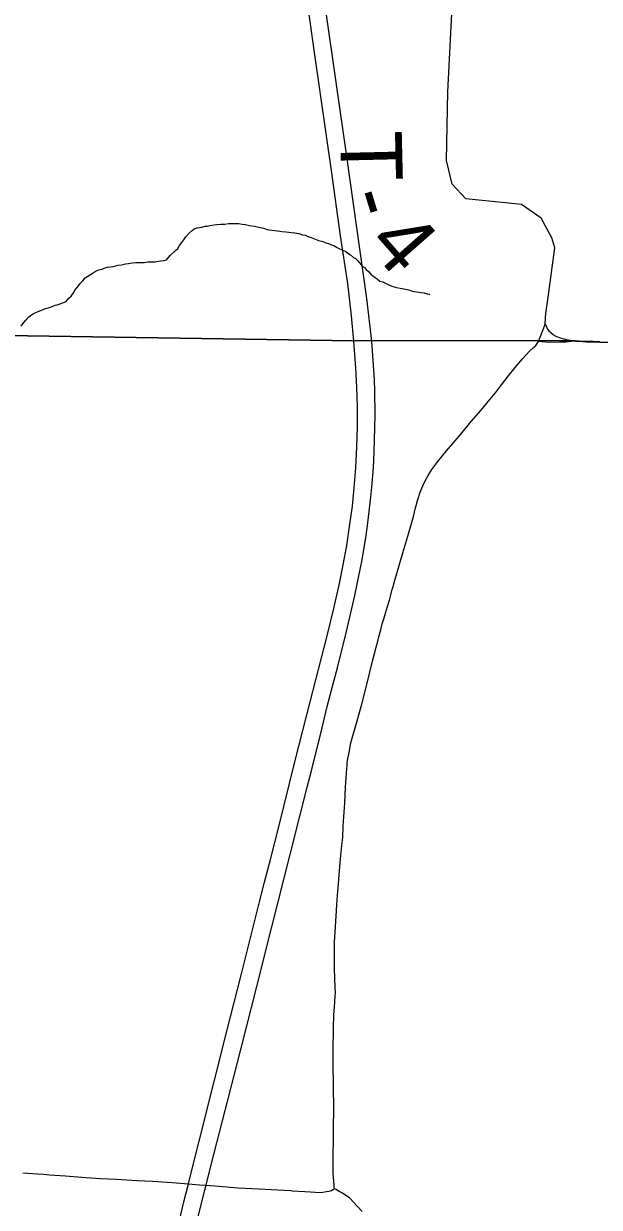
# Model space of a CAD drawing. Extents: x -14196 to 143, y -6096 to 28.
# Drawn here: x 60.591 to 61.122, y 18.007 to 19.098 of the extents above; entities that cross this region are included whole.
import ezdxf

# ---------------------------------------------------------------- set-up
doc = ezdxf.new("R2010")
doc.units = 0
for name, color, linetype in [('GM_X_Corporation', 7, 'Continuous'), ('GM_X_Interstate_Route', 7, 'Continuous'), ('GM_X_Minor_River', 7, 'Continuous'), ('GM_X_Township_Road', 7, 'Continuous'), ('GM_X_Township_Road_Text', 7, 'Continuous')]:
    doc.layers.add(name, color=color, linetype=linetype)

msp = doc.modelspace()

# ---------------------------------------------------------------- linework, layer by layer
at = {"layer": 'GM_X_Corporation'}
for points in [[(59.8722, 18.8218), (60.8954, 18.8061), (60.912, 18.8063), (61.0983, 18.8061), (61.0996, 18.806), (61.1035, 18.8058), (61.1096, 18.8055), (61.116, 18.8053), (61.1223, 18.8051)], [(61.1223, 18.8051), (61.116, 18.8053), (61.1096, 18.8055), (61.1035, 18.8058), (61.0996, 18.806), (61.0983, 18.8061), (60.912, 18.8063), (60.8954, 18.8061), (59.8722, 18.8218)], [(61.1223, 18.8051), (61.116, 18.8053), (61.1096, 18.8055), (61.1035, 18.8058), (61.0996, 18.806), (61.0983, 18.8061), (60.912, 18.8063), (60.8954, 18.8061), (59.8722, 18.8218)], [(59.8722, 18.8218), (60.8954, 18.8061), (60.912, 18.8063), (61.0983, 18.8061), (61.0996, 18.806), (61.1035, 18.8058), (61.1096, 18.8055), (61.116, 18.8053), (61.1223, 18.8051)]]:
    msp.add_lwpolyline(points, dxfattribs=at)
at = {"layer": 'GM_X_Interstate_Route'}
for points in [[(60.9122, 18.8058), (60.9074, 18.845), (60.8892, 18.9758), (60.8693, 19.1129), (60.8405, 19.3186), (60.8277, 19.4083), (60.8186, 19.4759), (60.8137, 19.5147), (60.8102, 19.5418), (60.8094, 19.5798), (60.8096, 19.619), (60.8115, 19.6474), (60.8138, 19.6739), (60.8196, 19.7099), (60.8268, 19.747)], [(60.8956, 18.8056), (60.8934, 18.8292), (60.8899, 18.8588), (60.8833, 18.9029), (60.8749, 18.9631), (60.8596, 19.0697), (60.8503, 19.1355), (60.8427, 19.1883), (60.8363, 19.235), (60.8284, 19.299), (60.8241, 19.3296), (60.8155, 19.3923), (60.8086, 19.4392), (60.8021, 19.4892), (60.7981, 19.524), (60.797, 19.5612), (60.797, 19.6), (60.796, 19.6301), (60.7968, 19.6533), (60.7993, 19.6773), (60.8042, 19.7129)], [(60.7311, 17.9793), (60.7389, 18.0125), (60.7431, 18.0291), (60.744, 18.033), (60.7529, 18.0686), (60.7671, 18.1246), (60.7785, 18.1697), (60.7919, 18.2227), (60.8087, 18.289), (60.8133, 18.307), (60.8186, 18.3281), (60.826, 18.357), (60.8412, 18.4179), (60.8523, 18.4612), (60.8712, 18.5353), (60.8772, 18.5594), (60.8823, 18.5825), (60.8858, 18.5996), (60.889, 18.6173), (60.892, 18.637), (60.8942, 18.6537), (60.8959, 18.6704), (60.8973, 18.689), (60.8983, 18.7082), (60.8988, 18.7269), (60.8988, 18.7456), (60.8984, 18.763), (60.8975, 18.781), (60.8956, 18.8056)], [(60.7518, 17.9978), (60.7581, 18.0232), (60.7593, 18.0279), (60.7641, 18.0466), (60.7769, 18.0966), (60.7852, 18.129), (60.7917, 18.1543), (60.8061, 18.2109), (60.8198, 18.2659), (60.8368, 18.3326), (60.8459, 18.3681), (60.8524, 18.3946), (60.8561, 18.4084), (60.8604, 18.426), (60.8634, 18.4367), (60.8664, 18.4494), (60.871, 18.4689), (60.8766, 18.4898), (60.8805, 18.5048), (60.8888, 18.538), (60.8965, 18.5712), (60.9017, 18.5968), (60.9031, 18.6041), (60.9068, 18.6267), (60.9085, 18.6384), (60.9113, 18.6618), (60.9122, 18.6711), (60.9136, 18.689), (60.9144, 18.7039), (60.915, 18.7256), (60.9151, 18.738), (60.9148, 18.7597), (60.9146, 18.7703), (60.9122, 18.8058)]]:
    msp.add_lwpolyline(points, dxfattribs=at)
at = {"layer": 'GM_X_Minor_River'}
for points in [[(60.589, 18.8194), (60.5912, 18.8229), (60.5931, 18.8252), (60.5957, 18.8279), (60.5976, 18.8294), (60.5998, 18.831), (60.6029, 18.8325), (60.607, 18.8341), (60.6097, 18.8352), (60.6127, 18.836), (60.615, 18.8368), (60.6176, 18.8376), (60.6202, 18.8388), (60.6221, 18.8392), (60.624, 18.8399), (60.6305, 18.8423), (60.6327, 18.8453), (60.635, 18.8473), (60.6372, 18.8503), (60.6387, 18.853), (60.6402, 18.8549), (60.6417, 18.8568), (60.6432, 18.8587), (60.6458, 18.8614), (60.648, 18.8641), (60.6503, 18.8656), (60.6529, 18.8672), (60.6552, 18.8687), (60.6571, 18.8699), (60.6597, 18.8711), (60.6616, 18.8718), (60.6635, 18.8722), (60.6654, 18.873), (60.6681, 18.8738), (60.6711, 18.8742), (60.6737, 18.8746), (60.6783, 18.8758), (60.6813, 18.8762), (60.6851, 18.877), (60.6878, 18.8774), (60.6912, 18.8778), (60.6946, 18.8782), (60.6984, 18.8783), (60.7022, 18.8783), (60.7056, 18.8787), (60.7086, 18.8788), (60.712, 18.8788), (60.7174, 18.8796), (60.7208, 18.88), (60.7227, 18.8808), (60.7264, 18.885), (60.7313, 18.8893), (60.7332, 18.8912), (60.7347, 18.8938), (60.7369, 18.8965), (60.7388, 18.8992), (60.7406, 18.9019), (60.7436, 18.9053), (60.7466, 18.9076), (60.7485, 18.9092), (60.7512, 18.91), (60.7534, 18.9104), (60.7553, 18.9108), (60.7584, 18.9116), (60.7603, 18.9116), (60.7629, 18.9124), (60.7667, 18.9128), (60.7694, 18.9132), (60.7728, 18.9136), (60.7766, 18.9136), (60.78, 18.9141), (60.7823, 18.9141), (60.7853, 18.9141), (60.7891, 18.9141), (60.7925, 18.9134), (60.7956, 18.9131), (60.7994, 18.9123), (60.8039, 18.9116), (60.8081, 18.9109), (60.8123, 18.9098), (60.8157, 18.9087), (60.8199, 18.908), (60.8226, 18.9076), (60.8256, 18.9073), (60.8291, 18.9069), (60.8329, 18.9066), (60.8355, 18.9063), (60.8382, 18.9059), (60.8412, 18.9056), (60.8447, 18.9048), (60.8481, 18.9037), (60.8511, 18.9034), (60.853, 18.9023), (60.8561, 18.9011), (60.8607, 18.8993), (60.863, 18.8986), (60.8656, 18.8978), (60.8679, 18.8971), (60.8698, 18.8963)], [(60.8698, 18.8963), (60.8721, 18.8956), (60.8748, 18.8945), (60.8771, 18.8938), (60.8801, 18.8919), (60.8824, 18.8908), (60.8855, 18.8897), (60.8882, 18.8882), (60.8901, 18.8867), (60.8924, 18.8852), (60.8951, 18.8829), (60.897, 18.8818), (60.8989, 18.8799), (60.9008, 18.878), (60.9035, 18.8746), (60.9054, 18.8735), (60.907, 18.8716), (60.9089, 18.8698), (60.9112, 18.8675), (60.9143, 18.8649), (60.9169, 18.863), (60.9196, 18.8611), (60.9223, 18.8604), (60.9246, 18.8593), (60.9273, 18.8578), (60.9307, 18.8563), (60.9349, 18.8552), (60.9383, 18.8545), (60.9402, 18.8541), (60.9463, 18.853), (60.9494, 18.8519), (60.9513, 18.8516), (60.9535, 18.8512), (60.9554, 18.8509), (60.9573, 18.8505), (60.9604, 18.8501), (60.9631, 18.8494), (60.965, 18.8491), (60.9657, 18.8491)]]:
    msp.add_lwpolyline(points, dxfattribs=at)
at = {"layer": 'GM_X_Township_Road'}
for points in [[(61.0659, 18.8055), (61.0715, 18.8203), (61.0719, 18.8221), (61.0726, 18.8316), (61.074, 18.8415), (61.0807, 18.8916), (61.0779, 18.901), (61.0681, 18.9189), (61.0502, 18.9316), (60.9987, 18.937), (60.9863, 18.9503), (60.9808, 18.9722), (60.9822, 19.0354), (60.9883, 19.1563)], [(61.0985, 18.8056), (61.093, 18.8066), (61.092, 18.8068), (61.0897, 18.8074), (61.0891, 18.8076), (61.087, 18.8082), (61.0845, 18.809), (61.0836, 18.8094), (61.0819, 18.8101), (61.0794, 18.8114), (61.0767, 18.8138), (61.0759, 18.8146), (61.0753, 18.8155), (61.0747, 18.8164), (61.0738, 18.8178), (61.073, 18.8194), (61.0726, 18.8203), (61.0719, 18.8221)], [(60.8778, 18.0246), (60.8775, 18.0264), (60.8773, 18.0286), (60.877, 18.0313), (60.8766, 18.039), (60.8765, 18.0523), (60.8767, 18.0731), (60.8769, 18.083), (60.877, 18.0963), (60.877, 18.1029), (60.8769, 18.1138), (60.8767, 18.1238), (60.8764, 18.1345), (60.8765, 18.1438), (60.8766, 18.1575), (60.8769, 18.1667), (60.8769, 18.1725), (60.8772, 18.1849), (60.8777, 18.192), (60.878, 18.1968), (60.8783, 18.2021), (60.8785, 18.2053), (60.8783, 18.21), (60.878, 18.2186), (60.8778, 18.2271), (60.8776, 18.237), (60.8776, 18.2446), (60.8777, 18.252), (60.8782, 18.2613), (60.8792, 18.2759), (60.8799, 18.2867), (60.8805, 18.2952), (60.8812, 18.3019), (60.8824, 18.3178), (60.8833, 18.3285), (60.8846, 18.3408), (60.8854, 18.3482), (60.8858, 18.3587), (60.8871, 18.3803), (60.8878, 18.3947), (60.8891, 18.412), (60.8893, 18.4144), (60.8894, 18.4167), (60.8897, 18.4193), (60.8911, 18.4267), (60.8929, 18.4356), (60.8992, 18.458), (60.9031, 18.4725), (60.9066, 18.4857), (60.9101, 18.4994), (60.913, 18.5119), (60.9161, 18.5236), (60.9176, 18.5291), (60.9186, 18.5331), (60.9203, 18.5398), (60.9218, 18.5451), (60.9235, 18.5507), (60.9248, 18.555), (60.9256, 18.5581), (60.9265, 18.5611), (60.9283, 18.567), (60.9295, 18.5719), (60.9306, 18.5758), (60.9317, 18.5796), (60.9331, 18.5841), (60.9352, 18.5917), (60.9408, 18.6106), (60.9453, 18.6261), (60.9493, 18.6397), (60.9505, 18.6441), (60.9525, 18.652), (60.9546, 18.6599), (60.9567, 18.6665), (60.959, 18.6724), (60.9612, 18.677), (60.964, 18.682), (60.9674, 18.6874), (60.9731, 18.6949), (60.981, 18.7047), (60.9926, 18.7182), (61.0037, 18.7316), (61.0127, 18.7419), (61.021, 18.7519), (61.0261, 18.7582), (61.0318, 18.7655), (61.0378, 18.7735), (61.0441, 18.7813), (61.051, 18.7894), (61.0574, 18.7964), (61.0611, 18.7998), (61.0634, 18.8017), (61.0659, 18.8055)], [(61.0985, 18.8056), (61.0909, 18.8047), (61.0855, 18.8047), (61.0757, 18.8046), (61.072, 18.8047), (61.0659, 18.8055)], [(61.2699, 18.8018), (61.2666, 18.8022), (61.2633, 18.8025), (61.2569, 18.8029), (61.2473, 18.8033), (61.241, 18.8036), (61.2288, 18.8034), (61.2072, 18.8038), (61.1829, 18.8046), (61.1745, 18.8049), (61.1665, 18.8052), (61.1558, 18.8051), (61.1499, 18.805), (61.1448, 18.805), (61.1389, 18.8048), (61.1327, 18.8046), (61.1277, 18.8044), (61.1225, 18.8046), (61.1162, 18.8047), (61.1098, 18.8049), (61.1037, 18.8053), (61.0998, 18.8055), (61.0985, 18.8056)], [(60.5904, 18.0392), (60.5951, 18.0389), (60.6039, 18.0383), (60.6094, 18.038), (60.6151, 18.0375), (60.6299, 18.0364), (60.6485, 18.035), (60.6619, 18.0341), (60.6767, 18.0334), (60.6958, 18.0323), (60.7098, 18.0315), (60.7282, 18.0303), (60.7431, 18.0291), (60.7532, 18.0283), (60.7593, 18.0279), (60.7713, 18.027), (60.7889, 18.0255), (60.8081, 18.0244), (60.8312, 18.0232), (60.8376, 18.0229), (60.8386, 18.0228)], [(60.8386, 18.0228), (60.8504, 18.0222), (60.8557, 18.0218), (60.86, 18.0214), (60.8633, 18.0213), (60.8669, 18.0215), (60.8703, 18.022), (60.8729, 18.0225), (60.8748, 18.0231), (60.8765, 18.0238), (60.8778, 18.0246)], [(60.9032, 18.0035), (60.899, 18.0083), (60.8955, 18.0121), (60.8914, 18.0161), (60.8873, 18.0189), (60.8852, 18.0204), (60.8821, 18.0221), (60.8806, 18.023), (60.8794, 18.0238), (60.8778, 18.0246)]]:
    msp.add_lwpolyline(points, dxfattribs=at)

# ---------------------------------------------------------------- texts
at = {"layer": 'GM_X_Township_Road_Text'}
for s, rotation, p in [('T', 271.3501, (60.8829, 18.9988)), ('-', 287.1378, (60.8867, 18.9395)), ('4', 311.2903, (60.9062, 18.8946))]:
    msp.add_text(s, height=0.0568, rotation=rotation, dxfattribs=at).set_placement(p)

doc.saveas('drawing.dxf')
